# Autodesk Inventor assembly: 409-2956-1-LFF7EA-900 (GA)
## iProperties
Created: 2010-09
Part Number: 409-2956-1-LFF7EA-900 (GA)
Document SubType Name: Assembly
Designer: S. Boerckel
Mass: 2.71449e+06 g
Surface Area: 794951 cm^2
Volume: 404621 cm^3
Density: 6.70872 g/cm^3
Description: GENERAL ARRANGEMENT UNIT 298034
Material: ASSEMBLY
SMR: =<MATERIAL>
Author: S. Boerckel
Revision Number: 0
Title: GENERAL ARRANGEMENT UNIT-298034
